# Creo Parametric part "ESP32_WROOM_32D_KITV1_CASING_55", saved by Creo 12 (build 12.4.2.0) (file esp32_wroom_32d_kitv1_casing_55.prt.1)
Units: Custom; MM, KILOGRAM, SECS

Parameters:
  PTC_WM_ITERATION = "0"
  PTC_WM_VERSION = "-.0"
  PTC_WM_LIFECYCLE_STATE = "In Work"
  PTC_WM_LIFECYCLE = "MO_CADDocument"
  PTC_WM_CREATED_BY = "Maximilian Roepper (Z0017RMS: MO)"
  PTC_WM_CREATED_ON = "18-Sep-26 11:36:42 AM"
  PTC_WM_MODIFIED_BY = "Maximilian Roepper (Z0017RMS: MO)"
  PTC_WM_MODIFIED_ON = "18-Sep-26 11:36:46 AM"
  PDMLINKNUMBER = "PDM000071454944"
  PTC_WM_NAME = "esp32_wroom_32d_kitv1_casing_55.prt"
  PTC_WM_NUMBER = "PDM000071454944"

Other parameters: WEIGHT, WEIGHT_FACTOR, WEIGHT_ADD, _MASS_TEMP, _DIFF_TEMP, MC_ERRORS, SUPPLIER

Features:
  1. coordinate system
  2. datum plane "PRT_YZ"
  3. datum plane "PRT_XY"
  4. datum plane "PRT_XZ"
  5. coordinate system
  6. datum axis
  7. datum axis
  8. datum axis
  9. coordinate system
  10. imported feature
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
Other named items: PRT, SIEMENS_MO, DRW_VIEW_ORG, PRT_X, PRT_Y, PRT_Z, CS0, ROUGH_GROB

Layers: 00_STD_CSYS-KSYS, 01_STD_PLANES-EBENEN, 02_STD_AXES-ACHSEN, 03_STD_CSYS-KSYS, 24_IMPORT_FEAT-IMPORT_KE

Surfaces: 5 plane, 1 cylinder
